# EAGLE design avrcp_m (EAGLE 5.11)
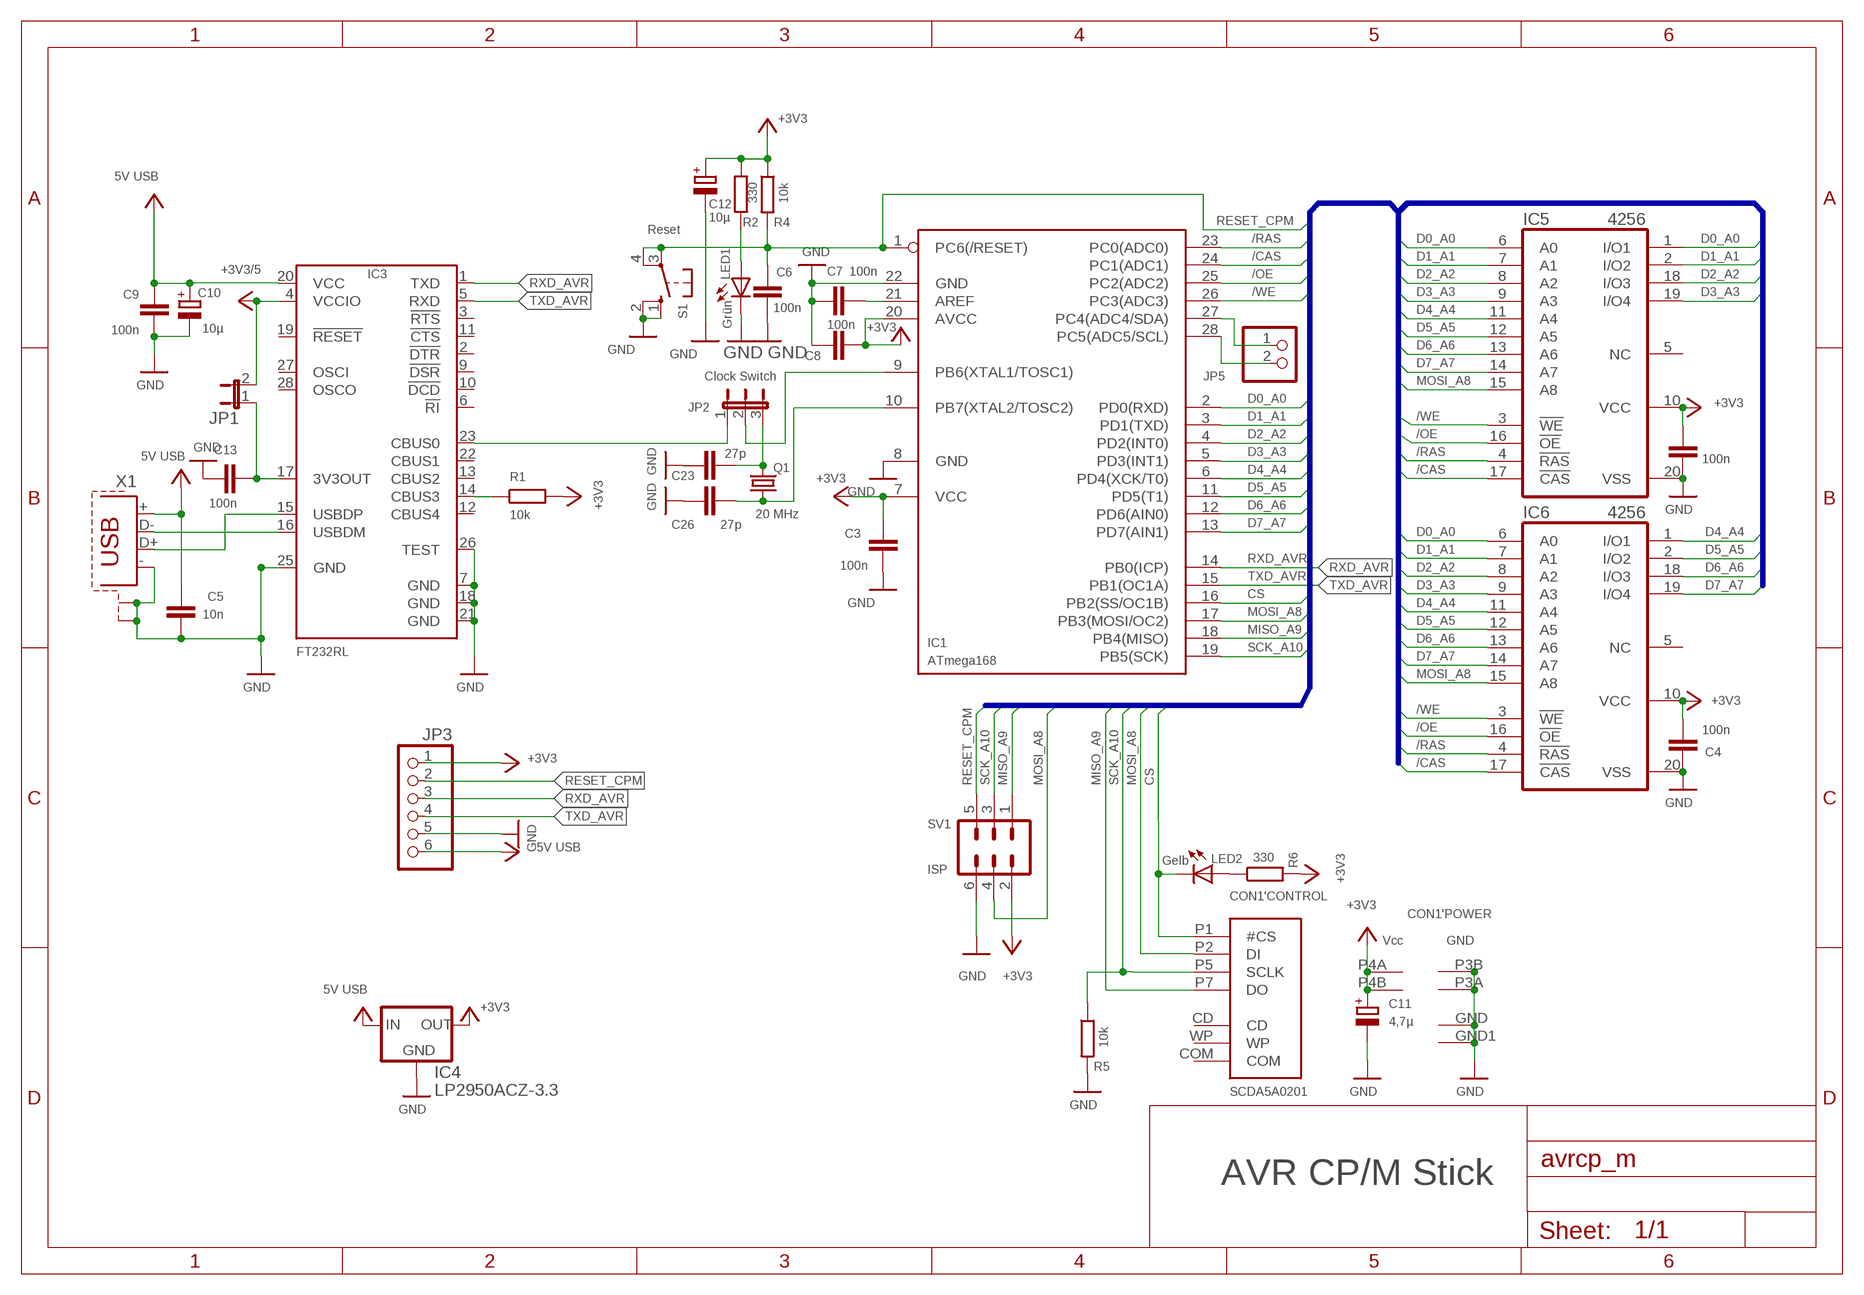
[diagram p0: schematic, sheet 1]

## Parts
C3  100n  C-EU025-024X044  [C025-024X044]
C4  100n  C-EU025-024X044  [C025-024X044]
C5  10n  C-EU025-024X044  [C025-024X044]
C6  100n  C-EU025-024X044  [C025-024X044]
C7  100n  C-EU025-024X044  [C025-024X044]
C8  100n  C-EU025-024X044  [C025-024X044]
C9  100n  C-EU025-024X044  [C025-024X044]
C10  10µ  CPOL-EUE2-5  [E2-5]
C11  4,7µ  CPOL-EUE2-4  [E2-4]
C12  10µ  CPOL-EUE2-4  [E2-4]
C13  100n  C-EU025-024X044  [C025-024X044]
C15  100n  C-EU025-024X044  [C025-024X044]
C23  27p  C-EU025-024X044  [C025-024X044]
C26  27p  C-EU025-024X044  [C025-024X044]
CON1  SCDA5A0201  [SCDA5A0201]
IC1  ATmega168  MEGA8-P  [DIL28-3]
IC3  FT232RL  [SSOP28]
IC4  LP2950ACZ-3.3  [TO92]
IC5  4256  514256ALP  [DIL20]
IC6  4256  514256ALP  [DIL20]
JP1  JP1E  [JP1]
JP2  Clock Switch  JP2E  [JP2]
JP3  PINHD-1X6  [1X06]
JP5  PINHD-1X2  [1X02]
LED1  Grün  LED3MM  [LED3MM]
LED2  Gelb  LED3MM  [LED3MM]
Q1  20 MHz  CRYSTALHC49S  [HC49/S]
R1  10k  R-EU_0207/7  [0207/7]
R2  330  R-EU_0207/7  [0207/7]
R4  10k  R-EU_0207/7  [0207/7]
R5  10k  R-EU_0204/7  [0204/7]
R6  330  R-EU_0204/7  [0204/7]
S1  Reset  10-XX  [B3F-10XX]
SV1  ISP  ML6  [ML6]
X1  AWF  [AWF]

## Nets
+3V3: C3.1 C4.2 C8.1 C11.+ C12.+ C15.2 CON1.P4A('POWER:VCC) CON1.P4B('POWER:VCC1) IC1.7(VCC) IC1.20(AVCC) IC3.4(VCCIO) IC4.1(OUT) IC5.10(VCC) IC6.10(VCC) JP1.2 JP3.1 R1.2 R2.2 R4.1 R6.2 SV1.2 ; supply symbol labelled +3V3/5
+5V: C5.2 C9.2 C10.+ IC3.20(VCC) IC4.3(IN) JP3.6 X1.+ ; supply symbol labelled 5V USB
/CAS: IC1.24(PC1(ADC1)) IC5.17(!CAS) IC6.17(!CAS)
/OE: IC1.25(PC2(ADC2)) IC5.16(!OE) IC6.16(!OE)
/RAS: IC1.23(PC0(ADC0)) IC5.4(!RAS) IC6.4(!RAS)
/WE: IC1.26(PC3(ADC3)) IC5.3(!WE) IC6.3(!WE)
CS: CON1.P1('CONTROL:#CS) IC1.16(PB2(SS/OC1B)) LED2.K(C)
D0_A0: IC1.2(PD0(RXD)) IC5.1(I/O1) IC5.6(A0) IC6.6(A0)
D1_A1: IC1.3(PD1(TXD)) IC5.2(I/O2) IC5.7(A1) IC6.7(A1)
D2_A2: IC1.4(PD2(INT0)) IC5.8(A2) IC5.18(I/O3) IC6.8(A2)
D3_A3: IC1.5(PD3(INT1)) IC5.9(A3) IC5.19(I/O4) IC6.9(A3)
D4_A4: IC1.6(PD4(XCK/T0)) IC5.11(A4) IC6.1(I/O1) IC6.11(A4)
D5_A5: IC1.11(PD5(T1)) IC5.12(A5) IC6.2(I/O2) IC6.12(A5)
D6_A6: IC1.12(PD6(AIN0)) IC5.13(A6) IC6.13(A6) IC6.18(I/O3)
D7_A7: IC1.13(PD7(AIN1)) IC5.14(A7) IC6.14(A7) IC6.19(I/O4)
GND: C3.2 C4.1 C5.1 C6.1 C7.2 C8.2 C9.1 C10.- C11.- C12.- C13.1 C15.1 C23.2 C26.2 CON1.GND1('POWER:GND) CON1.GND('POWER:GND) CON1.P3A('POWER:GND) CON1.P3B('POWER:GND) IC1.8(GND) IC1.22(GND) IC3.7(GND) IC3.18(GND) IC3.21(GND) IC3.25(GND) IC3.26(TEST) IC4.2(GND) IC5.20(VSS) IC6.20(VSS) JP3.5 LED1.K(C) R5.2 S1.1(S) S1.2(S1) SV1.6 X1.- X1.SHIELD1(S1) X1.SHIELD2(S2)
MISO_A9: CON1.P7('CONTROL:DO) IC1.18(PB4(MISO)) SV1.1
MOSI_A8: CON1.P2('CONTROL:DI) IC1.17(PB3(MOSI/OC2)) IC5.15(A8) IC6.15(A8) SV1.4
N$1: IC3.14(CBUS3) R1.1
N$2: C13.2 IC3.17(3V3OUT) JP1.1
N$3: C7.1 IC1.21(AREF)
N$4: IC1.9(PB6(XTAL1/TOSC1)) JP2.2
N$5: IC1.27(PC4(ADC4/SDA)) JP5.1
N$6: IC1.28(PC5(ADC5/SCL)) JP5.2
N$7: LED1.A R2.1
N$8: IC3.23(CBUS0) JP2.1
N$9: IC3.16(USBDM) X1.D-
N$10: IC3.15(USBDP) X1.D+
N$13: LED2.A R6.1
N$23: C26.1 IC1.10(PB7(XTAL2/TOSC2)) Q1.1
N$24: C23.1 JP2.3 Q1.2
RESET_CPM: C6.2 IC1.1(PC6(/RESET)) JP3.2 R4.2 S1.3(P) S1.4(P1) SV1.5
RXD_AVR: IC1.14(PB0(ICP)) IC3.1(TXD) JP3.3
SCK_A10: CON1.P5('CONTROL:SCLK) IC1.19(PB5(SCK)) R5.1 SV1.3
TXD_AVR: IC1.15(PB1(OC1A)) IC3.5(RXD) JP3.4
Unconnected: CON1.CD('CONTROL:CD) CON1.COM('CONTROL:COM) CON1.WP('CONTROL:WP) IC3.2(!DTR) IC3.3(!RTS) IC3.6(!RI) IC3.9(!DSR) IC3.10(!DCD) IC3.11(!CTS) IC3.12(CBUS4) IC3.13(CBUS2) IC3.19(!RESET) IC3.22(CBUS1) IC3.27(OSCI) IC3.28(OSCO) IC5.5(NC) IC6.5(NC)

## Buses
SCK_A10,MISO_A9,MOSI_A8,D7_A7,D6_A6,D5_A5,D4_A4,D3_A3,D2_A2,D1_A1,D0_A0,/WE,/OE,/RAS,/CAS,RESET_CPM,CS,SCK

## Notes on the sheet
- AVR CP/M Stick

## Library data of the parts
C3-C9 C13 C15 C23 C26 = rcl:C-EU: CAPACITOR, European symbol
C10-C12 = rcl:CPOL-EU: POLARIZED CAPACITOR, European symbol
CON1 = SCDA5A0201:SCDA5A0201: ALPS Connector for SDMemory Card SD-CARD SCDA5A0201 SPI -MODE
IC1 = atmel:MEGA8-P: MICROCONTROLLER 8 Kbytes FLASH, 1 kbytes SRAM, 512 bytes EEPROM, USART, 4-channel 10 bit ADC, 2-channel 8 bit ADC Pin compatible with Atmega48, ATMega88, ATMega168 Source: avr.lbr
IC3 = ftdichip:FT232R: Source: http://www.ftdichip.com/Documents/DataSheets/DS_FT232R_v104.pdf
IC4 = v-reg:LP2950?*: Source: http://cache.national.com/ds/LP/LP2950.pdf
IC5 IC6 = memory-hitachi:514256ALP: MEMORY
JP1 = jumper:JP1E: JUMPER
JP2 = jumper:JP2E: JUMPER
JP3 = pinhead:PINHD-1X6: PIN HEADER
JP5 = pinhead:PINHD-1X2: PIN HEADER
LED1 LED2 = led:LED: LED
Q1 = crystal:CRYSTAL: CRYSTAL
R1 R2 R4-R6 = rcl:R-EU_: RESISTOR, European symbol
S1 = switch-omron:10-XX: OMRON SWITCH
SV1 = con-harting-ml:ML6: HARTING
X1 = con-berg:AWF

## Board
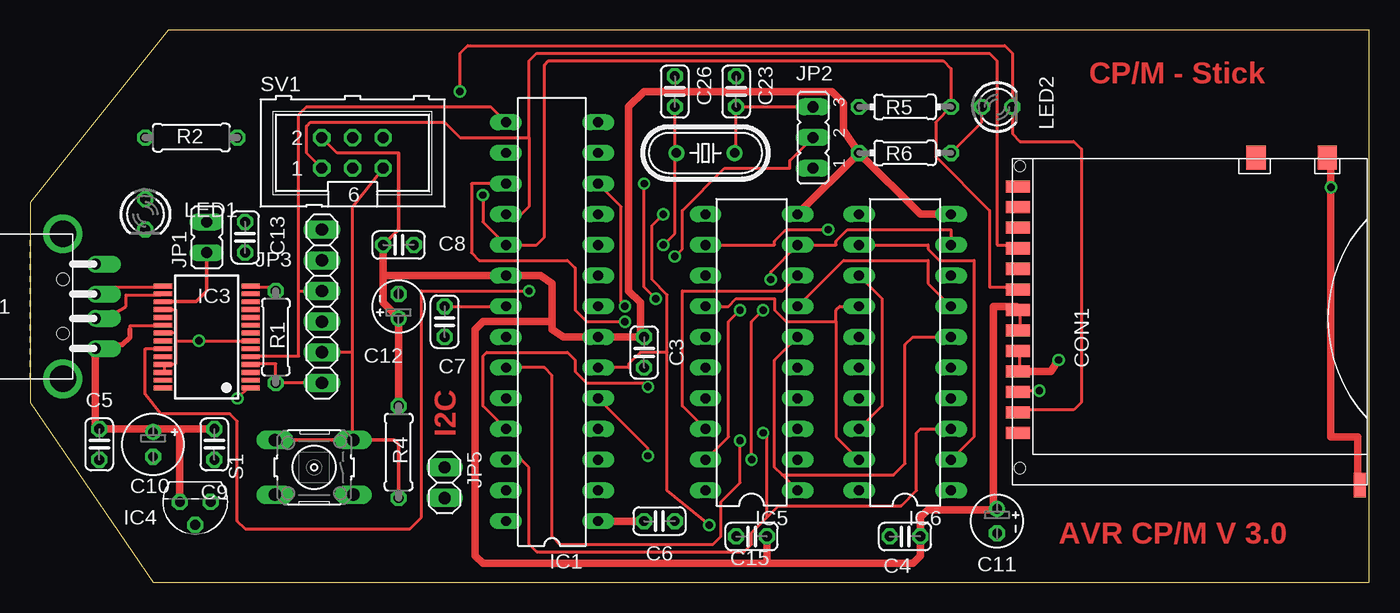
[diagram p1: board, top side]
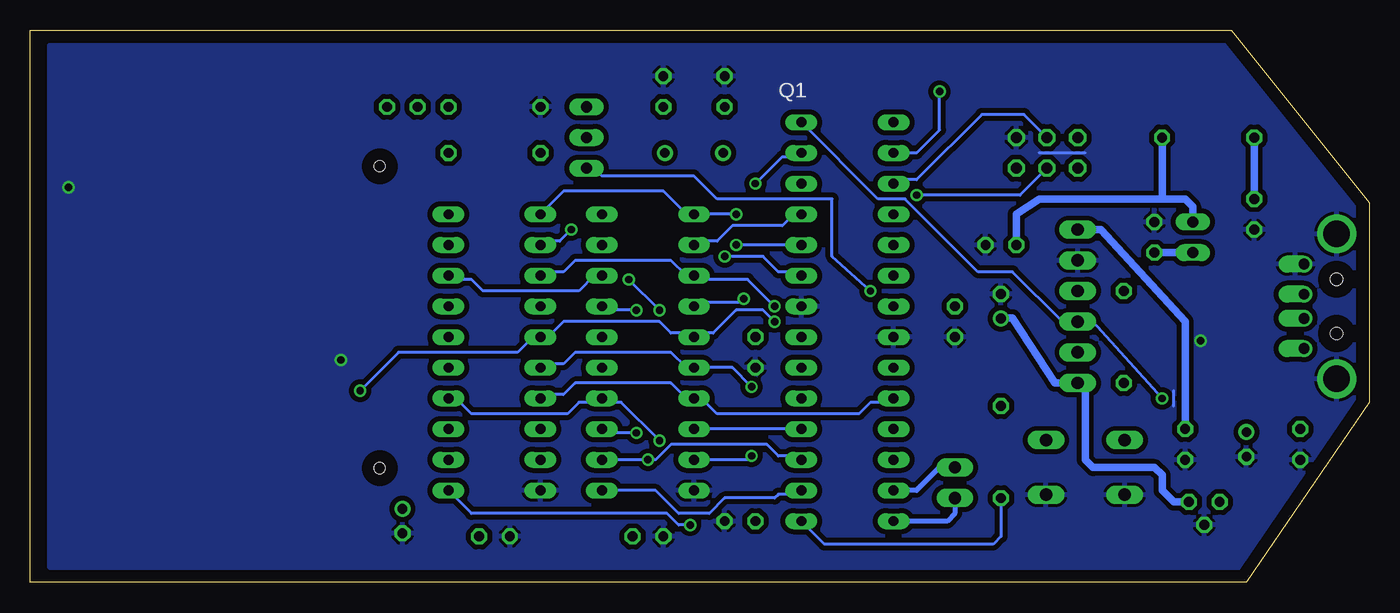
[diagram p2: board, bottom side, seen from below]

Size 110.81 x 45.72 mm. Coordinates in mm from the lower left corner, seen from the top.
Outline: 10.16,0 110.81,0 110.81,45.72 11.43,45.72 0,31.43 0,14.92 10.16,0
Copper layers (1*16): Top 0.035mm / dielectric 1.5mm / Bottom 0.035mm
Design rules "default": minimum track width 10mil, minimum drill 24mil, track to track 8mil, track to pad 8mil, pad to pad 8mil, via to via 8mil, smd to smd 8mil, copper to edge 40mil, drill to drill 8mil, minimum pad ring 10mil, minimum via ring 8mil, stop-mask expansion 4mil, vias tented up to drill 0mil, thermal gap 10mil

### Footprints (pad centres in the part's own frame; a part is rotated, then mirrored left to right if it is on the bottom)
C025-024X044 = drill 0.813 octagon: 1 -1.27,0; 2 1.27,0
E2-5 = drill 0.813 pad 1.27 round: + -1.016,0 | drill 0.813 pad 1.27 octagon: - 1.016,0
E2-4 = drill 0.813 pad 1.27 round: + -1.016,0 | drill 0.813 pad 1.27 octagon: - 1.016,0
SCDA5A0201 = smd 1 x 2: CD 9.475,-0.45; COM 11.175,-0.45; P1 -7.525,-0.45; P2 -5.825,-0.45; P3A -4.125,-0.45; P3B -2.425,-0.45; P4A -0.725,-0.45; P4B 0.975,-0.45; P5 2.675,-0.45; P6 4.375,-0.45; P7 6.075,-0.45; P8 7.775,-0.45; P9 -9.225,-0.45 | smd 2 x 1.6: GND 13.575,-26.05; WP 13.575,-20.15 | smd 2 x 1: GND1 -13.525,-28.75 | hole 0.9: -12.125,-0.6; 12.875,-0.6
DIL28-3 = drill 0.813 long: 1 -16.51,-3.81; 2 -13.97,-3.81; 3 -11.43,-3.81; 4 -8.89,-3.81; 5 -6.35,-3.81; 6 -3.81,-3.81; 7 -1.27,-3.81; 8 1.27,-3.81; 9 3.81,-3.81; 10 6.35,-3.81; 11 8.89,-3.81; 12 11.43,-3.81; 13 13.97,-3.81; 14 16.51,-3.81; 15 16.51,3.81; 16 13.97,3.81; 17 11.43,3.81; 18 8.89,3.81; 19 6.35,3.81; 20 3.81,3.81; 21 1.27,3.81; 22 -1.27,3.81; 23 -3.81,3.81; 24 -6.35,3.81; 25 -8.89,3.81; 26 -11.43,3.81; 27 -13.97,3.81; 28 -16.51,3.81
SSOP28 = smd 0.4 x 1.5: 1 -4.225,-3.625; 2 -3.575,-3.625; 3 -2.925,-3.625; 4 -2.275,-3.625; 5 -1.625,-3.625; 6 -0.975,-3.625; 7 -0.325,-3.625; 8 0.325,-3.625; 9 0.975,-3.625; 10 1.625,-3.625; 11 2.275,-3.625; 12 2.925,-3.625; 13 3.575,-3.625; 14 4.225,-3.625; 15 4.225,3.625; 16 3.575,3.625; 17 2.925,3.625; 18 2.275,3.625; 19 1.625,3.625; 20 0.975,3.625; 21 0.325,3.625; 22 -0.325,3.625; 23 -0.975,3.625; 24 -1.625,3.625; 25 -2.275,3.625; 26 -2.925,3.625; 27 -3.575,3.625; 28 -4.225,3.625
TO92 = drill 0.813 octagon: 1 -1.27,0; 2 0,1.905; 3 1.27,0
DIL20 = drill 0.813 long: 1 -11.43,-3.81; 2 -8.89,-3.81; 3 -6.35,-3.81; 4 -3.81,-3.81; 5 -1.27,-3.81; 6 1.27,-3.81; 7 3.81,-3.81; 8 6.35,-3.81; 9 8.89,-3.81; 10 11.43,-3.81; 11 11.43,3.81; 12 8.89,3.81; 13 6.35,3.81; 14 3.81,3.81; 15 1.27,3.81; 16 -1.27,3.81; 17 -3.81,3.81; 18 -6.35,3.81; 19 -8.89,3.81; 20 -11.43,3.81
JP1 = drill 0.914 long: 1 0,-1.27; 2 0,1.27
JP2 = drill 0.914 long: 1 -2.54,0; 2 0,0; 3 2.54,0
1X06 = drill 1.016 long: 1 -6.35,0; 2 -3.81,0; 3 -1.27,0; 4 1.27,0; 5 3.81,0; 6 6.35,0
1X02 = drill 1.016 long: 1 -1.27,0; 2 1.27,0
LED3MM = drill 0.813 octagon: A -1.27,0; K 1.27,0
HC49/S = drill 0.813 round: 1 -2.413,0; 2 2.413,0
0207/7 = drill 0.813 octagon: 1 -3.81,0; 2 3.81,0
0204/7 = drill 0.813 octagon: 1 -3.81,0; 2 3.81,0
B3F-10XX = drill 1.016 long: 1 -3.251,2.261; 2 3.251,2.261; 3 -3.251,-2.261; 4 3.251,-2.261
ML6 = drill 0.914 octagon: 1 -2.54,-1.27; 2 -2.54,1.27; 3 0,-1.27; 4 0,1.27; 5 2.54,-1.27; 6 2.54,1.27
AWF = drill 0.9 offset: + 5.4,-3.5; - 5.4,3.5; D+ 5.4,1; D- 5.4,-1 | drill 2.2 round: SHIELD1 2.7,6; SHIELD2 2.7,-6 | hole 1: 2.7,2.25; 2.7,-2.25

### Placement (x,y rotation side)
C3  50.8,19.05 270 top
C4  72.39,3.81 0 top
C5  5.71,11.43 90 top
C6  52.07,5.08 180 top
C7  34.29,21.59 270 top
C8  30.48,27.94 0 top
C9  15.24,11.43 90 top
C10  10.16,11.43 270 top
C11  80.01,5.08 270 top
C12  30.48,22.86 90 top
C13  17.78,28.57 270 top
C15  59.69,3.81 0 top
C23  58.42,40.64 90 top
C26  53.34,40.64 90 top
CON1  81.28,21.59 90 top
IC1  43.18,21.59 90 top
IC3  14.61,20.32 90 top
IC4  13.65,6.67 180 top
IC5  59.69,19.05 90 top
IC6  72.39,19.05 90 top
JP1  14.61,28.57 0 top
JP2  64.77,36.83 90 top
JP3  24.13,22.86 90 top
JP5  34.29,8.26 270 top
LED1  9.53,30.48 270 top
LED2  80.01,39.37 0 top
Q1  55.88,35.56 0 top
R1  20.32,20.32 270 top
R2  13.33,36.83 0 top
R4  30.48,10.79 270 top
R5  72.39,39.37 180 top
R6  72.39,35.56 180 top
S1  23.5,9.53 180 top
SV1  26.67,35.56 0 top
X1  0,22.86 0 top

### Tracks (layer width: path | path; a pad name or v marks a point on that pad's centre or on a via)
+3V3
  Top 0.254: 80.01,6.03 C11.+ 80.01,6.35 | CON1.P4A 81.92,20.95 81.92,22.54 CON1.P4B 81.6,22.86 | IC3.4 18.42,18.1 20.32,18.1 R1.2 JP3.1 | C12.+ 30.48,21.91 | SV1.2 25.4,35.56 30.48,35.56 | 50.48,20.32 C3.1
  Top 0.305: 30.48,35.56 30.48,29.21 C8.1
  Top 0.61: 60.96,1.59 73.03,1.59 73.66,2.22 C4.2 73.66,5.4 74.3,6.03 79.69,6.03 | 79.69,6.03 80.01,6.03 | R6.2 IC5.10 | 81.6,22.86 79.69,22.86 79.69,6.03 | R6.2 73.66,30.48 IC6.10 | 79.69,6.03 80.01,6.35 | 29.21,25.4 29.21,23.18 30.48,21.91 | 29.21,25.4 C8.1 | C12.+ R4.1 | 29.21,25.4 IC1.20 42.23,25.4 43.18,24.77 43.18,21.59 | 43.18,21.59 43.18,20.95 44.13,20.32 IC1.7 50.48,20.32 50.48,23.18 49.53,24.13 49.53,39.37 50.8,40.64 66.36,40.64 67.31,39.69 67.31,37.47 R6.2 | 43.18,21.59 37.46,21.59 36.83,20.95 36.83,2.22 37.46,1.59 60.96,1.59 | 60.96,1.59 C15.2
  Bottom 0.254: 30.48,21.91 C12.+
  Bottom 0.61: 30.48,21.91 29.53,21.91 26.04,16.51 JP3.1 23.5,16.51 23.5,10.16 22.86,9.53 17.78,9.53 17.15,8.89 17.15,7.62 16.19,6.67 IC4.1 | C8.1 29.21,30.48 27.31,31.75 17.15,31.75 | 17.15,31.75 R2.2 | 17.15,31.75 15.24,31.75 14.61,31.11 JP1.2
+5V
  Top 0.254: 10.16,12.7 C10.+ | 8.26,20.95 8.26,21.27 10.79,21.27 IC3.20
  Top 0.406: 8.26,20.95 8.26,20.32 7.62,19.68 5.72,19.68 X1.+
  Top 0.61: 12.7,12.7 10.16,12.7 C5.2 5.4,13.02 5.4,19.05 X1.+ | 12.7,12.7 C9.2 | IC4.3 12.38,12.38 12.7,12.7
  Bottom 0.61: JP3.6 22.23,29.21 15.24,21.59 C9.2
/CAS
  Bottom 0.254: IC1.24 39.69,14.92 41.27,14.92 42.23,13.97 53.98,13.97 55.24,15.24 IC5.17 56.52,15.24 57.78,16.51 65.72,16.51 66.68,15.56 68.26,15.56 IC6.17
/OE  (via drill 0.61)
  Top 0.254: IC1.25 37.46,14.61 37.46,18.73 37.78,19.05 44.45,19.05 45.09,18.41 45.09,17.46 46.04,16.51 51.12,16.51 v51.12,16.19
  Bottom 0.254: v51.12,16.19 52.7,17.78 IC5.16 56.52,17.78 57.78,19.05 65.72,19.05 66.68,18.1 68.26,18.1 IC6.16
/RAS  (via drill 0.61)
  Top 0.254: IC1.23 42.54,17.78 43.18,17.14 43.18,3.81 43.81,3.17 56.52,3.17 57.15,3.81 57.15,6.67 58.74,8.26 v58.74,11.75
  Bottom 0.254: 63.82,14.92 65.41,14.92 66.36,13.97 74.3,13.97 75.57,15.24 IC6.4 | v58.74,11.75 61.91,14.92 63.82,14.92 | 63.82,14.92 IC5.4
/WE  (via drill 0.61)
  Top 0.254: IC1.26 40.64,10.16 41.27,9.53 41.27,3.17 41.91,2.54 59.05,2.54 59.69,3.17 59.69,4.13 60.96,5.4 | 60.96,5.4 61.91,6.35 72.07,6.35 73.34,7.62 73.34,12.38 73.66,12.7 IC6.3 | v60.64,12.38 60.96,12.06 60.96,5.4
  Bottom 0.254: IC5.3 63.18,12.38 v60.64,12.38
CS  (via drill 0.61)
  Top 0.254: v35.56,40.64 35.56,43.81 36.2,44.45 80.65,44.45 81.28,43.81 LED2.K 81.28,37.15 81.92,36.51 86.36,36.51 87,35.88 87,14.92 86.36,14.29 81.92,14.29 CON1.P1
  Bottom 0.254: v35.56,40.64 35.56,37.47 37.46,35.56 IC1.16
D0_A0
  Top 0.254: IC5.6 61.59,18.41 61.59,9.53 62.23,8.89 | IC5.1 62.23,8.89 | IC6.6 73.03,20.32 72.39,19.68 72.39,9.84 71.44,8.89 62.23,8.89
  Bottom 0.254: IC1.2 47.31,7.3 48.89,7.3 49.21,6.99 53.34,6.99 54.61,5.71 57.15,5.71 59.05,7.62 IC5.1
D1_A1  (via drill 0.61)
  Top 0.254: IC5.7 67.31,26.67 74.3,26.67 74.3,24.77 IC6.7 | v60.64,22.54 59.69,21.59 v59.69,10.16
  Bottom 0.254: IC1.3 47.31,10.48 48.89,10.48 49.85,11.43 57.78,11.43 59.05,10.16 v59.69,10.16 IC5.2 | IC5.7 63.18,22.54 v60.64,22.54
D2_A2
  Top 0.254: IC5.8 62.23,24.13 53.98,24.13 53.98,14.61 IC5.18
  Bottom 0.254: IC1.4 IC5.18 | IC6.8 75.88,25.08 74.3,25.08 73.34,24.13 65.41,24.13 64.14,25.4 IC5.8
D3_A3  (via drill 0.61)
  Top 0.254: IC6.9 76.2,29.21 67.63,29.21 66.68,28.26 66.68,27.94 IC5.9 61.28,25.72 v61.28,25.08 | IC1.5 51.12,11.11 v51.12,10.48 | v58.74,22.54 57.78,21.59 57.78,12.06 IC5.19
  Bottom 0.254: v51.12,10.48 51.43,10.16 IC5.19 | v58.74,22.54 v61.28,25.08
D4_A4  (via drill 0.61)
  Top 0.254: IC1.6 49.53,17.78 49.53,18.1 50.48,19.05 52.7,19.05 | 52.7,19.05 52.7,7.62 v56.2,4.76 | v52.39,30.48 51.43,29.53 51.43,25.08 52.7,23.81 52.7,19.05
  Bottom 0.254: IC6.11 66.68,32.38 58.42,32.38 56.52,30.48 IC5.11 v52.39,30.48 | IC6.1 74.3,5.71 58.1,5.71 57.15,4.76 v56.2,4.76
D5_A5  (via drill 0.61)
  Top 0.254: IC6.12 74.3,27.94 74.3,27.62 75.25,26.67 78.11,26.67 78.11,12.06 IC6.2 | IC5.12 61.59,27.94 61.59,28.26 62.55,29.21 v66.04,29.21
  Bottom 0.254: IC5.12 55.56,28.26 53.98,28.26 52.7,29.53 48.58,29.53 47.62,30.48 IC1.11 | v66.04,29.21 66.99,28.26 68.26,28.26 IC6.12
D6_A6  (via drill 0.61)
  Top 0.254: IC6.18 70.48,14.61 70.48,23.5 IC6.13 | IC1.12 48.89,31.11 48.89,23.18 v49.21,22.86
  Bottom 0.254: IC6.13 68.26,25.72 66.68,25.72 65.72,26.67 57.78,26.67 56.52,25.4 IC5.13 55.56,25.08 51.43,25.08 v49.21,22.86
D7_A7  (via drill 0.61)
  Top 0.254: IC5.14 57.78,22.86 58.42,23.5 61.59,23.5 61.59,22.54 62.55,21.59 66.68,21.59 | 66.68,21.59 66.68,22.54 66.99,22.86 IC6.14 | IC6.19 66.68,12.06 66.68,21.59 | v50.8,33.02 50.8,24.45 v51.75,23.5
  Bottom 0.254: IC1.13 47.31,35.24 48.58,35.24 v50.8,33.02 | v51.75,23.5 52.07,23.18 55.56,23.18 IC5.14
GND  (via drill 0.61)
  Top 0.254: 11.11,18.1 11.11,17.46 IC3.26 | 12.06,20.64 11.11,20.64 IC3.21 | 12.06,20.64 12.06,22.54 11.11,22.54 IC3.18 | 12.06,20 v13.97,20 18.1,20 IC3.7 | 12.06,20 12.06,20.64 | 11.11,18.1 12.06,18.1 12.06,20 | 11.11,18.1 IC3.25 | 107.32,35.24 CON1.GND 107.63,34.92 | CON1.P3B 81.92,19.05 81.92,17.78 CON1.P3A 81.6,17.46 | CON1.GND1 110.17,8.89
  Top 0.61: 107.63,34.92 v107.63,32.7 107.63,12.06 109.86,12.06 109.86,8.24 CON1.GND1 | 81.6,17.46 84.45,17.46 v85.09,18.41
  Bottom 0.254: 23.5,35.56 27.31,35.56 | 16.19,14.61 16.19,15.88
  pour Bottom (isolate 0.406): 1.27,44.45 109.22,44.45 109.22,1.27 1.27,1.27
MISO_A9
  Top 0.254: 41.27,36.83 41.27,31.11 40.64,30.48 IC1.18 | 41.27,36.83 41.27,43.18 41.91,43.81 79.38,43.81 80.01,43.18 80.01,27.94 81.6,27.94 CON1.P7 | SV1.1 22.86,35.56 22.86,37.78 23.18,38.1 34.29,38.1 35.56,36.83 41.27,36.83
MOSI_A8  (via drill 0.61)
  Top 0.254: v83.5,15.88 81.92,15.88 CON1.P2 | IC1.17 36.51,33.02 36.51,27.3 37.15,26.67 44.45,26.67 45.09,26.04 45.09,22.54 46.04,21.59 v49.21,21.59
  Bottom 0.254: IC1.17 39.05,33.34 37.46,33.34 32.07,38.73 28.58,38.73 SV1.4 | v83.5,15.88 80.33,19.05 70.48,19.05 69.22,20.32 IC6.15 67.95,20.32 66.68,21.59 58.74,21.59 57.78,20.64 56.2,20.64 | v49.21,21.59 50.16,22.54 52.39,22.54 54.29,20.64 56.2,20.64 | 56.2,20.64 IC5.15
N$1
  Top 0.254: R1.1 20.32,24.45 18.42,24.45 IC3.14
N$2
  Top 0.305: IC3.17 13.72,23.25 14.61,24.13 JP1.1
  Bottom 0.61: JP1.1 C13.2
N$3
  Top 0.254: C7.1 IC1.21
N$4  (via drill 0.61)
  Top 0.254: v53.34,26.99 53.98,27.62 53.98,30.8 57.47,34.29 62.86,34.29 62.86,34.92 JP2.2
  Bottom 0.254: IC1.9 47.31,25.72 48.89,25.72 50.16,26.99 v53.34,26.99
N$5
  Bottom 0.406: IC1.27 37.46,7.62 35.56,9.53 JP5.1
N$6
  Bottom 0.406: IC1.28 34.92,5.08 34.29,5.71 JP5.2
N$7
  Bottom 0.61: LED1.A R2.1
N$8  (via drill 0.61)
  Top 0.254: v41.27,24.13 32.38,24.13 32.38,5.4 31.43,4.45 17.78,4.45 17.15,5.08 17.15,13.34 16.51,13.97 10.79,13.97 9.53,15.56 9.53,19.37 10.79,19.37 IC3.23
  Bottom 0.254: v41.27,24.13 44.45,26.99 44.45,31.75 53.98,31.75 55.88,33.66 63.5,33.66 64.14,34.29 JP2.1
N$9
  Top 0.254: IC3.16 10.79,23.81 7.94,23.81 7.94,22.86 6.35,21.91 5.71,21.91 X1.D-
N$10
  Top 0.254: IC3.15 10.79,24.45 5.71,24.45 5.71,24.13 X1.D+
N$13
  Top 0.254: R6.1 78.74,38.1 LED2.A
N$23  (via drill 0.61)
  Top 0.254: v52.39,27.94 53.34,28.89 53.34,35.56 | 53.34,35.56 C26.1 | 53.34,35.56 Q1.1
  Bottom 0.254: IC1.10 v52.39,27.94
N$24
  Top 0.254: Q1.2 58.42,35.56 C23.1 JP2.3
RESET_CPM
  Top 0.254: SV1.5 26.67,31.11 26.67,19.05 | 26.67,19.05 JP3.2 | 26.67,19.05 26.67,12.06 S1.3
  Top 0.305: S1.4 S1.3 30.12,11.79 30.48,11.43 R4.2
  Top 0.61: IC1.1 C6.2
  Bottom 0.254: IC1.1 45.09,3.17 31.12,3.17 30.48,3.81 R4.2
RXD_AVR  (via drill 0.61)
  Top 0.254: v17.15,15.24 18.1,16.19 IC3.1
  Bottom 0.254: v17.15,15.24 22.86,21.59 JP3.3 25.4,21.59 29.53,25.72 32.38,25.72 38.42,31.75 40.64,31.75 IC1.14
SCK_A10  (via drill 0.61)
  Top 0.254: CON1.P5 81.6,24.45 79.38,24.45 79.38,30.8 74.93,35.24 74.93,38.1 R5.1 76.2,42.55 75.57,43.18 42.86,43.18 42.54,42.86 42.54,28.57 41.91,27.94 IC1.19 37.46,29.84 v37.46,32.07
  Bottom 0.254: SV1.3 28.89,32.07 v37.46,32.07
TXD_AVR
  Top 0.254: 22.23,24.13 22.23,18.73 18.42,18.73 IC3.5 | 22.23,24.13 JP3.4 | IC1.15 38.1,39.37 22.86,39.37 22.23,38.73 22.23,24.13

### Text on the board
Top: CP/M - Stick | I2C | AVR CP/M V 3.0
